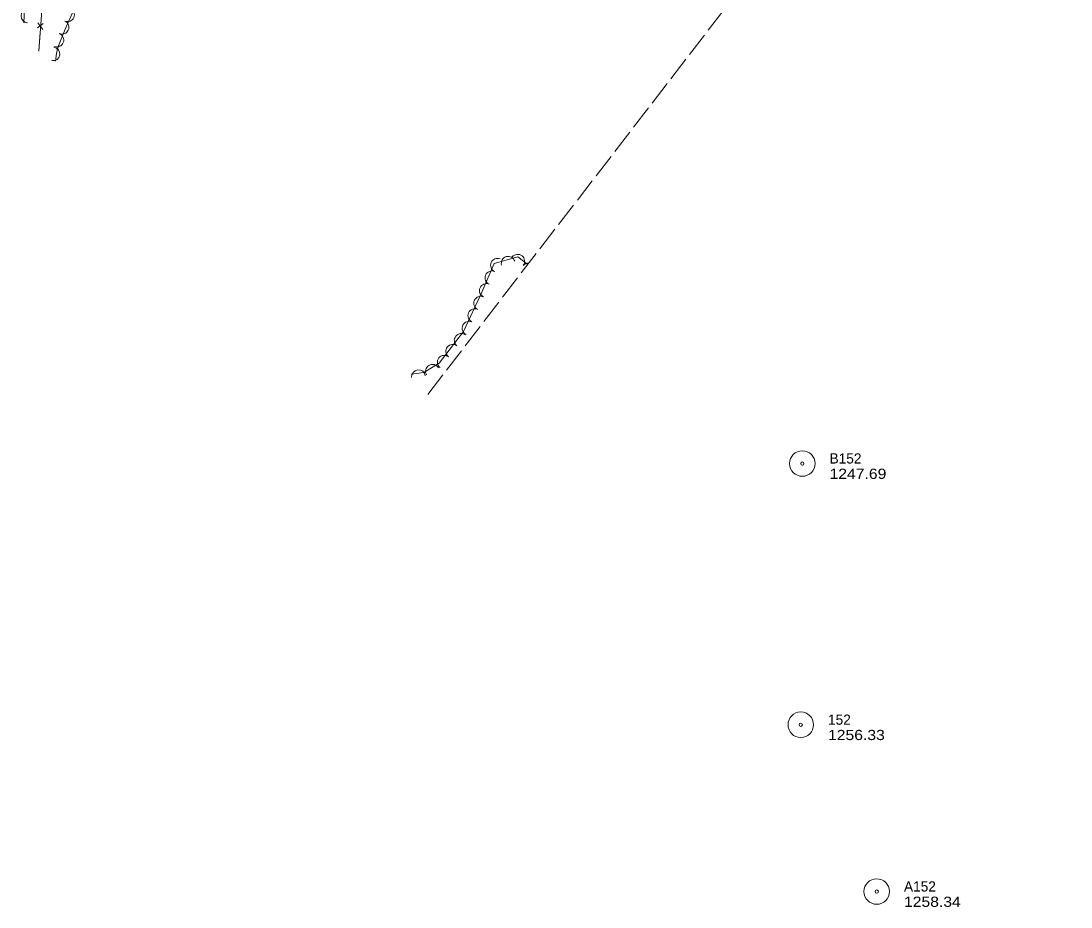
# Model space of a CAD drawing. Extents: x 299311 to 301657, y 49513 to 51866.
# Drawn here: x 300379 to 300996, y 49513 to 50034 of the extents above; entities that cross this region are included whole.
import ezdxf

# ---------------------------------------------------------------- set-up
doc = ezdxf.new("R2010")
doc.units = 0
doc.header["$LTSCALE"] = 2.4
doc.linetypes.add('LONG_DASHED', pattern=[7.5, 6, -1.5])
for name, color, linetype, lineweight in [('15', 7, 'Continuous', 13), ('18', 7, 'Continuous', 13), ('4', 7, 'Continuous', 13), ('6', 7, 'Continuous', 13)]:
    doc.layers.add(name, color=color, linetype=linetype, lineweight=lineweight)

msp = doc.modelspace()

# ---------------------------------------------------------------- linework, layer by layer
at = {"layer": '15'}
for p, q in [((300392.371, 50032.465), (300389.027, 50029.93)), ((300389.177, 50032.871), (300392.111, 50028.954)), ((300390.501, 50027.376), (300389.671, 50016.169))]:
    msp.add_line(p, q, dxfattribs=at)
msp.add_lwpolyline([(300825.105, 50257.815), (300812.538, 50222.335), (300764.322, 50225.321), (300715.715, 50226.496), (300671.678, 50227.929), (300567.676, 50228.641), (300558.07, 50135.432), (300471.877, 50140.966), (300398.833, 50143.747), (300394.186, 50077.12), (300389.671, 50016.169)], dxfattribs=at)
at = {"layer": '18'}
for points in [[(300381.807, 50052.692), (300381.01, 50032.869)], [(300399.538, 50010.259), (300400.175, 50014.671), (300400.893, 50018.279), (300405.196, 50029.103), (300409.998, 50040.021)], [(300676.832, 49890.782), (300670.996, 49895.393), (300657.196, 49891.442), (300649.81, 49874.553), (300639.169, 49851.489), (300624.726, 49832.924), (300615.842, 49827.434), (300608.374, 49826.496)]]:
    msp.add_lwpolyline(points, dxfattribs=at)
for centre, radius, start, end in [((300383.265, 50036.785), 4.004, 87.70528, 267.68996), ((300406.596, 50037.492), 4.004, 246.26661, 66.25129), ((300403.372, 50030.162), 4.004, 246.26661, 66.25129), ((300400.377, 50022.655), 4.004, 248.32774, 68.31242), ((300398.036, 50014.522), 4.004, 261.79213, 81.77681), ((300659.047, 49890.381), 4.053, 66.38665, 246.37133), ((300665.35, 49891.57), 4.053, 15.98431, 195.96899), ((300670.955, 49892.722), 4.053, 321.69546, 141.68013), ((300677.314, 49887.698), 4.053, 86.36888, 141.68013), ((300655.8, 49882.956), 4.053, 66.38665, 246.37133), ((300652.552, 49875.53), 4.053, 66.38665, 246.37133), ((300649.176, 49868.116), 4.053, 65.24056, 245.22523), ((300645.781, 49860.758), 4.053, 65.24056, 245.22523), ((300642.386, 49853.399), 4.053, 65.24056, 245.22523), ((300637.759, 49846.222), 4.053, 52.12584, 232.11052), ((300632.783, 49839.826), 4.053, 52.12584, 232.11052), ((300620.895, 49828.063), 4.053, 31.72227, 211.70695), ((300627.806, 49833.429), 4.053, 52.12584, 232.11052), ((300612.658, 49824.896), 4.053, 7.16667, 187.15135)]:
    msp.add_arc(centre, radius, start, end, dxfattribs=at)
at = {"layer": '4', "linetype": 'LONG_DASHED'}
msp.add_line((300618.12, 49814.518), (301331.18, 50740.757), dxfattribs=at)
at = {"layer": '6'}
for centre, radius in [((300838.065, 49773.9), 7.5), ((300838.065, 49773.9), 0.96), ((300837.159, 49620.469), 7.5), ((300837.159, 49620.469), 0.96), ((300881.762, 49522.502), 7.5), ((300881.762, 49522.502), 0.96)]:
    msp.add_circle(centre, radius, dxfattribs=at)

# ---------------------------------------------------------------- texts
for s, p in [('B152', (300854.065, 49773.9)), ('152', (300853.159, 49620.469)), ('A152', (300897.762, 49522.502))]:
    msp.add_text(s, height=6, dxfattribs=at).set_placement(p)
at = {"layer": '6', "width": 1.15}
for s, p in [('1247.69', (300854.065, 49764.9)), ('1256.33', (300853.159, 49611.469)), ('1258.34', (300897.762, 49513.502))]:
    msp.add_text(s, height=6, dxfattribs=at).set_placement(p)

doc.saveas('drawing.dxf')
